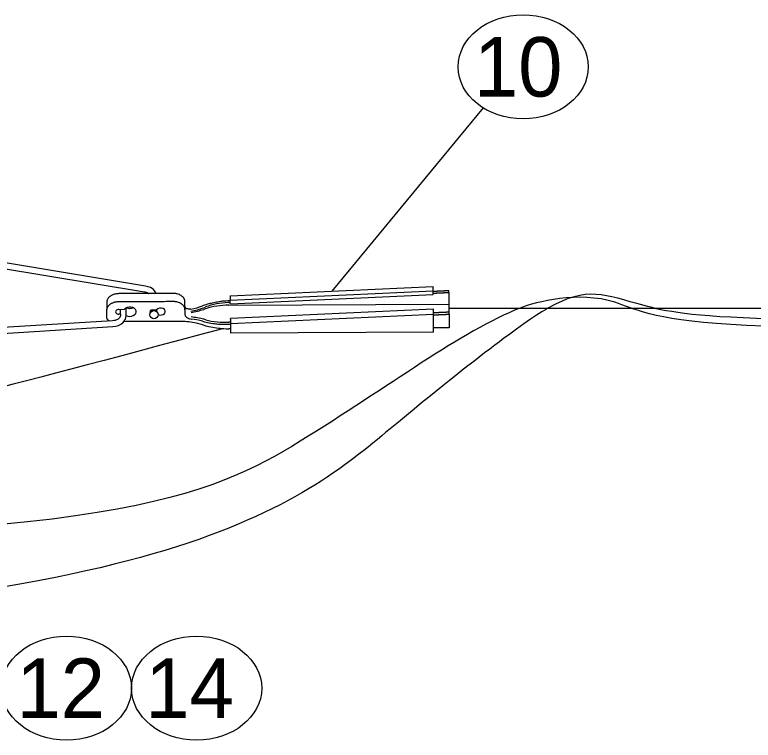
# Model space of a CAD drawing. Extents: x 99862 to 104211, y 98939 to 102076.
# Drawn here: x 102006.5 to 102205.1, y 101225.1 to 101420.1 of the extents above; entities that cross this region are included whole.
import ezdxf

# ---------------------------------------------------------------- set-up
doc = ezdxf.new("R2010")
doc.units = 0
for name, color, linetype in [('Level 12', 7, 'Continuous'), ('Level 13', 7, 'Continuous'), ('Level 14', 7, 'Continuous'), ('Level 15', 7, 'Continuous'), ('Level 16', 7, 'Continuous'), ('Level 20', 7, 'Continuous')]:
    doc.layers.add(name, color=color, linetype=linetype)

msp = doc.modelspace()

# ---------------------------------------------------------------- linework, layer by layer
at = {"layer": 'Level 12'}
msp.add_line((102123.27, 101341.26), (102367.23, 101341.26), dxfattribs=at)
msp.add_open_spline([(102062.44, 101335.69), (101998.25, 101318.55), (101954.14, 101307.33), (101926.64, 101304.24), (101926.64, 101304.98), (101880.31, 101304.22)], degree=3, dxfattribs=at)
at = {"layer": 'Level 13'}
for p, q in [((102123.26, 101345.47), (102123.26, 101346)), ((102123.26, 101345.47), (102123.26, 101342.36)), ((102057.53, 101342.02), (102057.01, 101341.83)), ((102057.34, 101341.37), (102057.86, 101341.55)), ((102064.07, 101343.3), (102064.07, 101343.3)), ((102064.08, 101342.05), (102123.26, 101342.36)), ((102123.26, 101342.36), (102123.29, 101340.15)), ((102031.31, 101338.73), (102031.29, 101340.86)), ((102033.65, 101340.26), (102033.65, 101340.26)), ((102034.54, 101340.92), (102036.03, 101340.93)), ((102034.93, 101339.62), (102034.54, 101339.62)), ((102039.19, 101340.31), (102039.19, 101340.31)), ((102042.86, 101340.31), (102042.86, 101340.31)), ((102043.53, 101340.81), (102043.56, 101340.81)), ((102043.53, 101340.81), (102044.65, 101340.81)), ((102057.86, 101341.09), (102057.34, 101340.92)), ((102123.33, 101339.62), (102123.32, 101340.16)), ((102123.33, 101339.62), (102123.33, 101335.94)), ((102057.05, 101337.75), (102057.58, 101337.61)), ((102057.9, 101338.1), (102057.37, 101338.24))]:
    msp.add_line(p, q, dxfattribs=at)
for centre, major_axis, ratio, start_param, end_param in [((102037.49, 101340.29), (1.71, 0.02), 0.733102, 4.089045, 8.867269), ((102045.74, 101340.33), (1.28, 0.01), 0.733102, 4.162793, 8.867269), ((102050.34, 101351.18), (15.6, 1.17), 0.67835, 4.892925, 5.102334), ((102064.19, 101332.68), (-15.61, -1.17), 0.67835, 4.988139, 5.102334), ((102064.19, 101332.68), (-14.82, -1.11), 0.67835, 4.684474, 5.102334), ((102064.19, 101331.96), (14.84, 0), 0.680094, 1.578471, 2.011587), ((102064.19, 101332.68), (-14.82, -1.11), 0.67835, 4.66921, 4.684474), ((102034.54, 101340.27), (0.891, 0.01), 0.733102, 1.562523, 4.704116), ((102037.46, 101342.41), (-1.71, -0.02), 0.733102, 1.013822, 2.12777), ((102043.53, 101340.32), (0.669, 0.008), 0.733102, 1.562523, 3.789204), ((102050.34, 101351.18), (16.39, 1.23), 0.67835, 4.882099, 5.102334), ((102050.34, 101351.01), (16.41, 0), 0.680094, 4.933161, 5.153179), ((102050.6, 101327.8), (-16.39, -1.23), 0.67835, 4.236103, 4.456343), ((102050.6, 101327.8), (-15.6, -1.17), 0.67835, 4.236103, 4.445518), ((102064.02, 101347.55), (15.6, 1.17), 0.67835, 4.236103, 4.350263), ((102064.02, 101347.55), (14.82, 1.11), 0.67835, 4.236103, 4.669219)]:
    msp.add_ellipse(centre, major_axis=major_axis, ratio=ratio, start_param=start_param, end_param=end_param, dxfattribs=at)
for points, degree in [([(102119.06, 101345.81), (102121.16, 101345.9), (102123.26, 101346)], 2), ([(102119.06, 101345.28), (102120.46, 101345.34), (102121.86, 101345.4), (102123.26, 101345.47)], 2), ([(102050.46, 101345.01), (102050.23, 101345.08), (102050, 101345.14), (102049.64, 101345.19), (102049.52, 101345.2), (102049.28, 101345.21), (102048.66, 101345.21), (102047.07, 101345.2), (102043.63, 101345.18), (102039.7, 101345.16), (102036.51, 101345.15), (102035.16, 101345.14), (102034.79, 101345.14), (102034.54, 101345.14), (102034.17, 101345.14), (102033.81, 101345.1), (102033.33, 101344.99), (102033.09, 101344.92), (102032.66, 101344.74), (102032.45, 101344.63), (102032.09, 101344.37), (102031.93, 101344.23), (102031.65, 101343.92), (102031.54, 101343.76), (102031.38, 101343.41), (102031.32, 101343.23), (102031.29, 101342.95), (102031.29, 101342.86), (102031.29, 101342.68), (102031.29, 101342.41), (102031.29, 101341.77), (102031.29, 101341.22), (102031.29, 101340.86)], 3), ([(102052.28, 101342.96), (102052.28, 101343.03), (102052.27, 101343.09), (102052.26, 101343.28), (102052.24, 101343.39), (102052.17, 101343.61), (102052.12, 101343.72), (102052, 101343.93), (102051.93, 101344.03), (102051.7, 101344.32), (102051.49, 101344.49), (102051.02, 101344.79), (102050.75, 101344.91), (102050.46, 101345.01)], 3), ([(102031.31, 101338.73), (102031.31, 101339.1), (102031.31, 101339.65), (102031.31, 101340.28), (102031.31, 101340.56), (102031.31, 101340.74), (102031.31, 101340.83), (102031.35, 101341.1), (102031.4, 101341.28), (102031.56, 101341.63), (102031.67, 101341.79), (102031.94, 101342.1), (102032.1, 101342.24), (102032.46, 101342.49), (102032.66, 101342.6), (102033.09, 101342.79), (102033.32, 101342.86), (102033.8, 101342.96), (102034.04, 101343), (102034.41, 101343.01), (102034.54, 101343.01), (102034.78, 101343.01), (102035.15, 101343.01), (102036.5, 101343.02), (102039.7, 101343.04), (102043.63, 101343.06), (102047.07, 101343.08), (102048.55, 101343.08), (102049.16, 101343.09), (102049.28, 101343.09), (102049.53, 101343.08), (102049.65, 101343.06), (102050.02, 101343.01), (102050.26, 101342.96), (102050.48, 101342.88)], 3), ([(102050.48, 101342.88), (102050.77, 101342.79), (102051.04, 101342.65), (102051.51, 101342.33), (102051.71, 101342.14), (102051.95, 101341.82), (102052.02, 101341.71), (102052.14, 101341.49), (102052.19, 101341.37), (102052.26, 101341.14), (102052.28, 101341.02), (102052.3, 101340.79), (102052.3, 101340.67), (102052.3, 101340.32), (102052.3, 101340.09), (102052.3, 101339.74), (102052.29, 101339.62), (102052.33, 101339.39), (102052.46, 101339.04), (102052.79, 101338.74), (102053.33, 101338.45), (102053.64, 101338.35), (102053.95, 101338.32)], 3), ([(102052.3, 101340.78), (102052.29, 101341.46), (102052.28, 101342.24), (102052.28, 101343.05)], 2), ([(102053.92, 101340.98), (102053.62, 101340.91), (102053.31, 101340.93), (102052.77, 101341.1), (102052.55, 101341.25), (102052.35, 101341.55), (102052.31, 101341.66), (102052.29, 101341.77)], 3), ([(102059.18, 101342.54), (102059.93, 101342.75), (102060.69, 101342.91), (102062.25, 101343.16), (102063.04, 101343.24), (102063.83, 101343.29)], 3), ([(102063.83, 101343.29), (102063.95, 101343.29), (102064.07, 101343.3)], 2), ([(102064.07, 101343.3), (102064.28, 101343.31), (102064.5, 101343.32)], 2), ([(102064.08, 101342.77), (102064.22, 101342.78), (102064.36, 101342.78), (102064.5, 101342.79)], 2), ([(102123.32, 101340.16), (102121.92, 101340.09), (102120.52, 101340.03), (102119.12, 101339.96)], 2), ([(102119.13, 101339.43), (102121.23, 101339.53), (102123.33, 101339.62)], 2), ([(102031.99, 101337.79), (102031.92, 101337.83), (102031.85, 101337.87), (102031.64, 101338.02), (102031.52, 101338.15), (102031.35, 101338.43), (102031.31, 101338.58), (102031.31, 101338.73)], 3), ([(102050.48, 101337.69), (102047.14, 101337.67), (102042.28, 101337.65), (102037.41, 101337.62), (102035.89, 101337.61)], 3), ([(102057.05, 101336.74), (102056.02, 101337.06), (102054.95, 101337.3), (102052.75, 101337.62), (102051.62, 101337.7), (102050.48, 101337.69)], 3), ([(102064.56, 101337.48), (102064.42, 101337.47), (102064.28, 101337.46), (102064.14, 101337.46)], 2), ([(102064.14, 101335.63), (102063.01, 101335.63), (102061.89, 101335.71), (102059.69, 101336.02), (102058.61, 101336.26), (102057.05, 101336.74)], 3), ([(102059.24, 101337.24), (102060.03, 101337.09), (102060.84, 101337), (102062.48, 101336.89), (102063.31, 101336.89), (102064.14, 101336.92)], 3), ([(102064.14, 101336.92), (102064.36, 101336.93), (102064.57, 101336.94)], 2), ([(102064.57, 101335.64), (102064.36, 101335.64), (102064.14, 101335.64)], 2), ([(102123.33, 101335.94), (102121.23, 101335.93), (102119.13, 101335.92)], 2)]:
    msp.add_open_spline(points, degree=degree, dxfattribs=at)
at = {"layer": 'Level 14'}
for p, q in [((102064.49, 101344.55), (102119.04, 101347.08)), ((102064.5, 101343.38), (102119.06, 101345.91)), ((102119.06, 101345.91), (102119.04, 101347.08)), ((102064.49, 101344.55), (102064.5, 101343.38)), ((102064.51, 101342.38), (102119.06, 101344.91)), ((102119.06, 101344.91), (102119.06, 101345.03)), ((102064.51, 101342.49), (102064.51, 101342.38)), ((102119.11, 101340.98), (102064.56, 101338.44)), ((102064.57, 101337.11), (102119.13, 101339.64)), ((102119.13, 101339.64), (102119.11, 101340.81)), ((102119.13, 101334.82), (102119.13, 101339.64)), ((102064.56, 101338.28), (102064.57, 101337.11)), ((102064.57, 101337.11), (102064.57, 101334.54)), ((102064.57, 101335.64), (102064.57, 101335.64)), ((102064.57, 101335.64), (102064.57, 101335.64)), ((102119.13, 101334.82), (102064.57, 101334.54))]:
    msp.add_line(p, q, dxfattribs=at)
for centre, start_param, end_param in [((102119.06, 101345.45), 3.965269, 5.536065), ((102064.5, 101342.92), 3.965269, 5.536065), ((102119.11, 101340.35), 5.536065, 6.283417), ((102064.56, 101337.82), 5.536065, 6.283417)]:
    msp.add_ellipse(centre, major_axis=(-0.003, 0.626), ratio=0.005626, start_param=start_param, end_param=end_param, dxfattribs=at)
msp.add_open_spline([(102064.57, 101335.64), (102064.57, 101335.64), (102064.57, 101335.64), (102064.57, 101335.64)], degree=2, dxfattribs=at)
at = {"layer": 'Level 15'}
for p, q in [((102132.49, 101395.08), (102091.77, 101345.81)), ((102041.66, 101347.17), (101967.8, 101359.37)), ((101967.54, 101357.83), (102041.4, 101345.63)), ((102034.92, 101340.93), (102034.93, 101340.27)), ((102034.93, 101340.27), (102034.94, 101339.19)), ((102036.49, 101340.29), (102036.48, 101341.29)), ((102036.5, 101339.21), (102036.49, 101340.29)), ((102043.18, 101340.73), (102043.18, 101340.26)), ((102044.75, 101340.28), (102044.74, 101340.91)), ((102032.83, 101337.85), (101966.59, 101333.75)), ((101966.68, 101332.19), (102032.93, 101336.29))]:
    msp.add_line(p, q, dxfattribs=at)
msp.add_circle((102043.97, 101339.48), 1.11, dxfattribs=at)
for centre, major_axis, ratio, start_param, end_param in [((102041.53, 101346.4), (-0.127, -0.771), 0.172997, 3.141579, 3.141593), ((102035.71, 101340.28), (-0.781, -0.009), 0.733102, 3.141581, 3.141604), ((102035.72, 101339.2), (-0.781, -0.009), 0.733102, 3.141581, 3.141593)]:
    msp.add_ellipse(centre, major_axis=major_axis, ratio=ratio, start_param=start_param, end_param=end_param, dxfattribs=at)
for points, degree in [([(102041.4, 101345.63), (102041.86, 101345.55), (102042.28, 101345.38), (102042.58, 101345.18)], 2), ([(102044.53, 101345.19), (102044.48, 101345.31), (102043.98, 101346.31), (102042.81, 101346.98), (102041.66, 101347.17)], 3), ([(102034.94, 101339.19), (102034.94, 101339.05), (102034.87, 101338.77), (102034.27, 101338.16), (102033.4, 101337.88), (102032.83, 101337.85)], 3), ([(102032.93, 101336.29), (102034.11, 101336.36), (102035.89, 101337.11), (102036.51, 101338.63), (102036.5, 101339.21)], 3)]:
    msp.add_open_spline(points, degree=degree, dxfattribs=at)
at = {"layer": 'Level 16'}
for points in [[(102333.14, 101341.26), (102186.03, 101330.44), (102169.52, 101348.95), (102146.65, 101342.91), (102142.45, 101341.28)], [(102333.14, 101341.26), (102203.46, 101335.63), (102169.6, 101342.41), (102160.42, 101347.25), (102150.05, 101341.31)], [(102150.05, 101341.31), (102144.38, 101338.07), (102118.28, 101319.1), (102049, 101258.95), (101870.11, 101256.31)], [(102142.43, 101341.27), (102126.79, 101335.17), (102087.07, 101304.71), (102032.13, 101277.19), (101871.2, 101280.29)]]:
    msp.add_open_spline(points, degree=3, dxfattribs=at)
at = {"layer": 'Level 20'}
for centre in [(102143.25, 101406.13), (102020.44, 101239.07), (102055.44, 101239.07)]:
    msp.add_ellipse(centre, major_axis=(-17.5, 0), ratio=0.8, dxfattribs=at)

# ---------------------------------------------------------------- texts
for s, p in [('10', (102130, 101398.13)), ('12', (102007.01, 101231.07)), ('14', (102041.66, 101231.07))]:
    msp.add_text(s, height=16, dxfattribs=at).set_placement(p)

doc.saveas('drawing.dxf')
